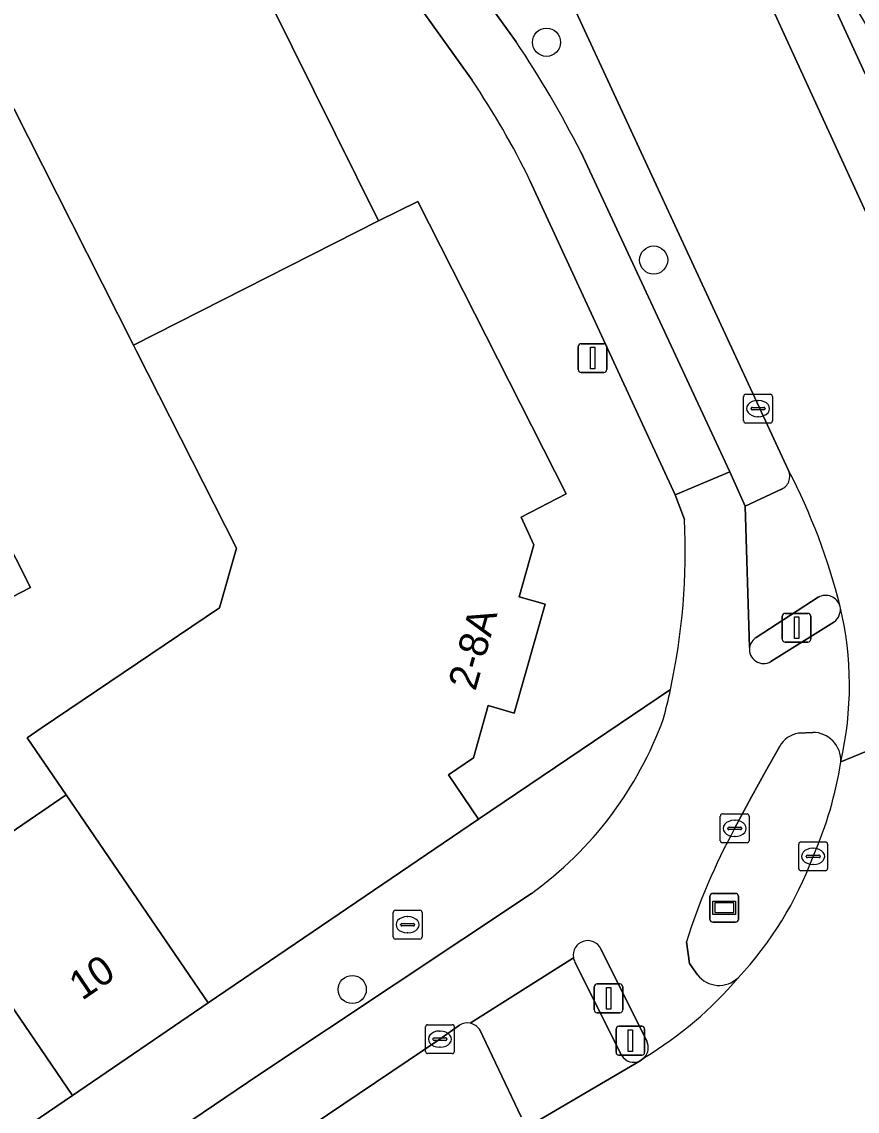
# Model space of a CAD drawing. Extents: x 161838 to 162344, y 381620 to 382160.
# Drawn here: x 162293.12 to 162322.12, y 381677.36 to 381715.15 of the extents above; entities that cross this region are included whole.
import ezdxf

# ---------------------------------------------------------------- set-up
doc = ezdxf.new("R2010")
doc.units = 0
for name, color, linetype in [('IMGEO_Berm_groen', 7, 'Continuous'), ('IMGEO_Boom', 7, 'Continuous'), ('IMGEO_Brandkraan', 7, 'Continuous'), ('IMGEO_Erf', 7, 'Continuous'), ('IMGEO_Fietspad_open', 7, 'Continuous'), ('IMGEO_Kolk', 7, 'Continuous'), ('IMGEO_Lichtmast', 7, 'Continuous'), ('IMGEO_Pand', 7, 'Continuous'), ('IMGEO_Pand_nummerreeks', 7, 'Continuous'), ('IMGEO_Rijbaan_lokaal_gesloten', 7, 'Continuous'), ('IMGEO_Rijbaan_lokaal_open', 7, 'Continuous'), ('IMGEO_Rijbaan_regionaal_gesloten', 7, 'Continuous'), ('IMGEO_Verkeerseiland_open', 7, 'Continuous'), ('IMGEO_Verkeersregelinstallatiepaal', 7, 'Continuous'), ('IMGEO_Voetpad_gesloten', 7, 'Continuous'), ('IMGEO_Voetpad_open', 7, 'Continuous'), ('IMGEO_Wegwijzer', 7, 'Continuous')]:
    doc.layers.add(name, color=color, linetype=linetype)

msp = doc.modelspace()

# ---------------------------------------------------------------- linework, layer by layer
at = {"layer": 'IMGEO_Berm_groen'}
for points in [[(162306.86, 381722.485), (162305.205, 381721.481), (162310.281, 381714.458)], [(162319.738, 381699.582), (162310.249, 381720.064)], [(162312.521, 381710.633), (162317.695, 381699.539), (162318.226, 381698.345), (162319.487, 381698.934)]]:
    msp.add_lwpolyline(points, dxfattribs=at)
for centre, radius, start, end in [((162279.374, 381693.79), 37.181, 26.9367, 33.7715), ((162319.293, 381699.382), 0.488, 293.3838, 24.2689)]:
    msp.add_arc(centre, radius, start, end, dxfattribs=at)
at = {"layer": 'IMGEO_Boom'}
for centre in [(162311.332, 381714.439), (162315.052, 381706.885), (162304.588, 381681.579)]:
    msp.add_circle(centre, 0.489, dxfattribs=at)
at = {"layer": 'IMGEO_Brandkraan'}
for p, q in [((162306.01, 381683.401), (162306.01, 381684.253)), ((162306.085, 381684.327), (162306.937, 381684.327)), ((162307.011, 381684.253), (162307.011, 381683.401)), ((162306.269, 381683.821), (162306.269, 381683.833)), ((162306.312, 381683.87), (162306.71, 381683.87)), ((162306.498, 381684.107), (162306.523, 381684.107)), ((162306.753, 381683.833), (162306.753, 381683.821)), ((162306.707, 381683.784), (162306.309, 381683.784)), ((162306.521, 381683.547), (162306.496, 381683.547)), ((162306.937, 381683.327), (162306.085, 381683.327))]:
    msp.add_line(p, q, dxfattribs=at)
for points in [[(162306.01, 381683.401), (162306.01, 381684.253)], [(162306.085, 381684.327), (162306.937, 381684.327)], [(162307.011, 381684.253), (162307.011, 381683.401)], [(162306.937, 381683.327), (162306.085, 381683.327)]]:
    msp.add_lwpolyline(points, dxfattribs=at)
for centre, radius, start, end in [((162306.087, 381684.251), 0.0765, 91.552, 178.448), ((162306.087, 381684.251), 0.0765, 91.552, 178.448), ((162306.935, 381684.251), 0.0765, 1.552, 88.448), ((162306.935, 381684.251), 0.0765, 1.552, 88.448), ((162306.309, 381683.83), 0.0403, 85.8775, 175.7526), ((162306.306, 381683.82), 0.0366, 178.938, 274.7102), ((162306.71, 381683.827), 0.043, 264.8664, 352.4533), ((162306.714, 381683.832), 0.0386, 1.7309, 96.639), ((162306.087, 381683.403), 0.0765, 181.552, 268.448), ((162306.087, 381683.403), 0.0765, 181.552, 268.448), ((162306.935, 381683.403), 0.0765, 271.552, 358.448), ((162306.935, 381683.403), 0.0765, 271.552, 358.448)]:
    msp.add_arc(centre, radius, start, end, dxfattribs=at)
for centre, major_axis, ratio, start_param, end_param in [((162306.497, 381683.827), (-0.387, 0.002), 0.722429, 4.712389, 7.853982), ((162306.522, 381683.827), (-0.39, 0.002), 0.717154, 1.570796, 4.712389)]:
    msp.add_ellipse(centre, major_axis=major_axis, ratio=ratio, start_param=start_param, end_param=end_param, dxfattribs=at)
at = {"layer": 'IMGEO_Erf'}
for points in [[(162289.948, 381685.116), (162294.655, 381688.332), (162293.298, 381690.315), (162293.785, 381690.643), (162299.981, 381694.821), (162300.565, 381696.886), (162297.099, 381703.727), (162296.995, 381703.932), (162294.839, 381708.188), (162287.364, 381722.942)], [(162290.874, 381700.53), (162293.422, 381695.521), (162291.191, 381694.385)]]:
    msp.add_lwpolyline(points, dxfattribs=at)
at = {"layer": 'IMGEO_Fietspad_open'}
for points in [[(162318.384, 381693.449), (162318.226, 381698.345), (162317.695, 381699.539), (162315.798, 381698.734), (162316.121, 381697.884)], [(162321.313, 381694.326), (162319.125, 381692.96)], [(162320.081, 381690.47), (162320.574, 381690.497)], [(162317.864, 381687.169), (162318.445, 381688.26), (162318.933, 381689.143), (162319.427, 381690.017)], [(162310.812, 381684.914), (162301.343, 381678.613), (162286.165, 381668.36), (162279.678, 381664.016), (162284.442, 381665.356), (162285.99, 381665.89), (162288.456, 381667.106), (162291.599, 381668.782), (162293.515, 381669.819)], [(162316.573, 381682.089), (162316.296, 381682.485), (162316.189, 381683.238)], [(162308.686, 381680.406), (162312.266, 381682.682)], [(162313.219, 381682.99), (162314.814, 381679.786)], [(162307.627, 381679.859), (162308.313, 381680.341)], [(162293.74, 381670.507), (162294.263, 381670.865), (162307.627, 381679.859)]]:
    msp.add_lwpolyline(points, dxfattribs=at)
for centre, radius, start, end in [((162293.525, 381696.773), 22.623, 347.7837, 2.8144), ((162320.985, 381694.769), 0.551, 306.4822, 10.5702), ((162309.989, 381692.125), 11.86, 347.1048, 13.384), ((162318.867, 381693.375), 0.489, 171.2798, 301.877), ((162294.156, 381696.632), 21.977, 345.1018, 347.7945), ((162303.284, 381695.362), 12.877, 305.7717, 340.1147), ((162320.224, 381689.565), 0.916, 98.9778, 150.4398), ((162320.577, 381689.523), 0.974, 357.3695, 90.161), ((162337.855, 381676.328), 22.741, 151.5304, 162.3118), ((162312.765, 381682.768), 0.506, 26.0677, 189.7529), ((162307.977, 381690.441), 13.099, 301.0544, 319.8015), ((162317.323, 381682.671), 0.95, 217.8161, 313.9029), ((162308.582, 381679.902), 0.515, 78.2993, 121.4712), ((162314.363, 381679.561), 0.504, 317.4307, 26.4792)]:
    msp.add_arc(centre, radius, start, end, dxfattribs=at)
at = {"layer": 'IMGEO_Kolk'}
for p, q in [((162318.177, 381701.304), (162318.177, 381702.156)), ((162318.252, 381702.23), (162319.104, 381702.23)), ((162318.665, 381702.01), (162318.69, 381702.01)), ((162319.178, 381702.156), (162319.178, 381701.304)), ((162318.436, 381701.724), (162318.436, 381701.736)), ((162318.874, 381701.687), (162318.476, 381701.687)), ((162318.479, 381701.773), (162318.877, 381701.773)), ((162318.92, 381701.736), (162318.92, 381701.724)), ((162319.104, 381701.23), (162318.252, 381701.23)), ((162318.688, 381701.45), (162318.663, 381701.45)), ((162317.367, 381686.742), (162317.367, 381687.594)), ((162317.442, 381687.668), (162318.294, 381687.668)), ((162318.368, 381687.594), (162318.368, 381686.742)), ((162317.669, 381687.211), (162318.067, 381687.211)), ((162317.855, 381687.448), (162317.88, 381687.448)), ((162317.626, 381687.162), (162317.626, 381687.174)), ((162318.064, 381687.125), (162317.666, 381687.125)), ((162317.878, 381686.888), (162317.853, 381686.888)), ((162318.11, 381687.174), (162318.11, 381687.162)), ((162318.294, 381686.668), (162317.442, 381686.668)), ((162320.089, 381685.771), (162320.089, 381686.623)), ((162320.164, 381686.697), (162321.016, 381686.697)), ((162320.577, 381686.477), (162320.602, 381686.477)), ((162321.09, 381686.623), (162321.09, 381685.771)), ((162320.348, 381686.191), (162320.348, 381686.203)), ((162320.786, 381686.154), (162320.388, 381686.154)), ((162320.391, 381686.24), (162320.789, 381686.24)), ((162320.832, 381686.203), (162320.832, 381686.191)), ((162321.016, 381685.697), (162320.164, 381685.697)), ((162320.6, 381685.917), (162320.575, 381685.917)), ((162307.131, 381679.432), (162307.131, 381680.284)), ((162307.206, 381680.358), (162308.058, 381680.358)), ((162307.619, 381680.138), (162307.644, 381680.138)), ((162308.132, 381680.284), (162308.132, 381679.432)), ((162307.39, 381679.852), (162307.39, 381679.864)), ((162307.828, 381679.815), (162307.43, 381679.815)), ((162307.433, 381679.901), (162307.831, 381679.901)), ((162307.874, 381679.864), (162307.874, 381679.852)), ((162308.058, 381679.358), (162307.206, 381679.358)), ((162307.642, 381679.578), (162307.617, 381679.578))]:
    msp.add_line(p, q, dxfattribs=at)
for points in [[(162318.177, 381701.304), (162318.177, 381702.156)], [(162318.252, 381702.23), (162319.104, 381702.23)], [(162319.178, 381702.156), (162319.178, 381701.304)], [(162319.104, 381701.23), (162318.252, 381701.23)], [(162317.367, 381686.742), (162317.367, 381687.594)], [(162317.442, 381687.668), (162318.294, 381687.668)], [(162318.368, 381687.594), (162318.368, 381686.742)], [(162318.294, 381686.668), (162317.442, 381686.668)], [(162320.089, 381685.771), (162320.089, 381686.623)], [(162320.164, 381686.697), (162321.016, 381686.697)], [(162321.09, 381686.623), (162321.09, 381685.771)], [(162321.016, 381685.697), (162320.164, 381685.697)], [(162307.131, 381679.432), (162307.131, 381680.284)], [(162307.206, 381680.358), (162308.058, 381680.358)], [(162308.132, 381680.284), (162308.132, 381679.432)], [(162308.058, 381679.358), (162307.206, 381679.358)]]:
    msp.add_lwpolyline(points, dxfattribs=at)
for centre, radius, start, end in [((162318.254, 381702.154), 0.0765, 91.552, 178.448), ((162318.254, 381702.154), 0.0765, 91.552, 178.448), ((162319.102, 381702.154), 0.0765, 1.552, 88.448), ((162319.102, 381702.154), 0.0765, 1.552, 88.448), ((162318.476, 381701.733), 0.0403, 85.8775, 175.7526), ((162318.473, 381701.723), 0.0366, 178.938, 274.7102), ((162318.877, 381701.73), 0.043, 264.8664, 352.4533), ((162318.881, 381701.735), 0.0386, 1.7309, 96.639), ((162318.254, 381701.306), 0.0765, 181.552, 268.448), ((162318.254, 381701.306), 0.0765, 181.552, 268.448), ((162319.102, 381701.306), 0.0765, 271.552, 358.448), ((162319.102, 381701.306), 0.0765, 271.552, 358.448), ((162317.444, 381687.592), 0.0765, 91.552, 178.448), ((162317.444, 381687.592), 0.0765, 91.552, 178.448), ((162318.292, 381687.592), 0.0765, 1.552, 88.448), ((162318.292, 381687.592), 0.0765, 1.552, 88.448), ((162317.666, 381687.171), 0.0403, 85.8775, 175.7526), ((162318.071, 381687.173), 0.0386, 1.7309, 96.639), ((162317.663, 381687.161), 0.0366, 178.938, 274.7102), ((162318.067, 381687.168), 0.043, 264.8664, 352.4533), ((162317.444, 381686.744), 0.0765, 181.552, 268.448), ((162317.444, 381686.744), 0.0765, 181.552, 268.448), ((162318.292, 381686.744), 0.0765, 271.552, 358.448), ((162318.292, 381686.744), 0.0765, 271.552, 358.448), ((162320.166, 381686.621), 0.0765, 91.552, 178.448), ((162320.166, 381686.621), 0.0765, 91.552, 178.448), ((162321.014, 381686.621), 0.0765, 1.552, 88.448), ((162321.014, 381686.621), 0.0765, 1.552, 88.448), ((162320.388, 381686.2), 0.0403, 85.8775, 175.7526), ((162320.385, 381686.19), 0.0366, 178.938, 274.7102), ((162320.789, 381686.197), 0.043, 264.8664, 352.4533), ((162320.793, 381686.202), 0.0386, 1.7309, 96.639), ((162320.166, 381685.773), 0.0765, 181.552, 268.448), ((162320.166, 381685.773), 0.0765, 181.552, 268.448), ((162321.014, 381685.773), 0.0765, 271.552, 358.448), ((162321.014, 381685.773), 0.0765, 271.552, 358.448), ((162307.208, 381680.282), 0.0765, 91.552, 178.448), ((162307.208, 381680.282), 0.0765, 91.552, 178.448), ((162308.056, 381680.282), 0.0765, 1.552, 88.448), ((162308.056, 381680.282), 0.0765, 1.552, 88.448), ((162307.43, 381679.861), 0.0403, 85.8775, 175.7526), ((162307.427, 381679.851), 0.0366, 178.938, 274.7102), ((162307.831, 381679.858), 0.043, 264.8664, 352.4533), ((162307.835, 381679.863), 0.0386, 1.7309, 96.639), ((162307.208, 381679.434), 0.0765, 181.552, 268.448), ((162307.208, 381679.434), 0.0765, 181.552, 268.448), ((162308.056, 381679.434), 0.0765, 271.552, 358.448), ((162308.056, 381679.434), 0.0765, 271.552, 358.448)]:
    msp.add_arc(centre, radius, start, end, dxfattribs=at)
for centre, major_axis, ratio, start_param, end_param in [((162318.664, 381701.73), (-0.387, 0.002), 0.722429, 4.712389, 7.853982), ((162318.689, 381701.73), (-0.39, 0.002), 0.717154, 1.570796, 4.712389), ((162317.854, 381687.168), (-0.387, 0.002), 0.722429, 4.712389, 7.853982), ((162317.879, 381687.168), (-0.39, 0.002), 0.717154, 1.570796, 4.712389), ((162320.576, 381686.197), (-0.387, 0.002), 0.722429, 4.712389, 7.853982), ((162320.601, 381686.197), (-0.39, 0.002), 0.717154, 1.570796, 4.712389), ((162307.618, 381679.858), (-0.387, 0.002), 0.722429, 4.712389, 7.853982), ((162307.643, 381679.858), (-0.39, 0.002), 0.717154, 1.570796, 4.712389)]:
    msp.add_ellipse(centre, major_axis=major_axis, ratio=ratio, start_param=start_param, end_param=end_param, dxfattribs=at)
at = {"layer": 'IMGEO_Lichtmast'}
for p, q in [((162312.437, 381703.082), (162312.437, 381703.882)), ((162312.437, 381703.882), (162312.437, 381703.082)), ((162312.537, 381703.982), (162313.327, 381703.982)), ((162313.327, 381703.982), (162312.537, 381703.982)), ((162313.427, 381703.882), (162313.427, 381703.082)), ((162313.427, 381703.082), (162313.427, 381703.882)), ((162313.327, 381702.982), (162312.537, 381702.982)), ((162312.537, 381702.982), (162313.327, 381702.982))]:
    msp.add_line(p, q, dxfattribs=at)
msp.add_lwpolyline([(162312.857, 381703.857), (162313.007, 381703.857), (162313.007, 381703.107), (162312.857, 381703.107), (162312.857, 381703.857)], dxfattribs=at)
for centre, start, end in [((162312.537, 381703.882), 90, 180), ((162312.537, 381703.882), 90, 180), ((162313.327, 381703.882), 0, 90), ((162313.327, 381703.882), 360, 90), ((162312.537, 381703.082), 180, 270), ((162312.537, 381703.082), 180, 270), ((162313.327, 381703.082), 270, 0), ((162313.327, 381703.082), 270, 0)]:
    msp.add_arc(centre, 0.1, start, end, dxfattribs=at)
at = {"layer": 'IMGEO_Pand'}
for points in [[(162296.995, 381703.932), (162305.503, 381708.242), (162301.748, 381715.79), (162303.026, 381716.487), (162300.998, 381720.448), (162299.66, 381719.808), (162295.769, 381727.423), (162287.364, 381722.942), (162294.839, 381708.188)], [(162310.379, 381695.201), (162310.892, 381697.01), (162310.45, 381697.966), (162312.016, 381698.769), (162306.867, 381708.921), (162305.503, 381708.242), (162296.995, 381703.932), (162297.099, 381703.727), (162300.565, 381696.886), (162299.981, 381694.821), (162293.785, 381690.643), (162293.298, 381690.315), (162294.655, 381688.332), (162299.588, 381681.111), (162308.972, 381687.49), (162307.931, 381689.021), (162308.795, 381689.617), (162309.308, 381691.426), (162310.212, 381691.169), (162311.283, 381694.945)], [(162294.655, 381688.332), (162289.948, 381685.116), (162294.874, 381677.907), (162299.588, 381681.111)], [(162289.948, 381685.116), (162285.24, 381681.899), (162290.158, 381674.701), (162294.874, 381677.907)]]:
    msp.add_lwpolyline(points, close=True, dxfattribs=at)
at = {"layer": 'IMGEO_Rijbaan_lokaal_gesloten'}
for points in [[(162326.921, 381698.993), (162325.155, 381702.899), (162324.878, 381703.181), (162301.871, 381753.308)], [(162295.695, 381751.431), (162310.161, 381720.255), (162310.249, 381720.064), (162319.738, 381699.582)], [(162333.756, 381695.892), (162318.739, 381721.3), (162322.39, 381713.347)], [(162321.55, 381689.478), (162328.954, 381692.519), (162328.07, 381695.334), (162326.956, 381698.551), (162326.909, 381698.657)]]:
    msp.add_lwpolyline(points, dxfattribs=at)
for centre, radius, start, end in [((162300.507, 381689.585), 21.674, 14.1133, 27.4671), ((162309.989, 381692.125), 11.86, 347.1048, 13.384)]:
    msp.add_arc(centre, radius, start, end, dxfattribs=at)
at = {"layer": 'IMGEO_Rijbaan_lokaal_open'}
msp.add_lwpolyline([(162291.191, 381694.385), (162293.422, 381695.521), (162290.874, 381700.53)], dxfattribs=at)
at = {"layer": 'IMGEO_Rijbaan_regionaal_gesloten'}
for points in [[(162328.954, 381692.519), (162321.55, 381689.478)], [(162314.734, 381679.22), (162314.585, 381679.105), (162310.64, 381676.791), (162310.287, 381676.584), (162311.76, 381673.667), (162313.323, 381670.573), (162313.719, 381670.825), (162317.538, 381673.258), (162320.432, 381675.065), (162321.734, 381675.903)]]:
    msp.add_lwpolyline(points, dxfattribs=at)
for centre, radius, start, end in [((162308.384, 381691.56), 13.33, 336.2733, 351.0119), ((162308.954, 381690.484), 12.398, 316.735, 339.7695), ((162307.977, 381690.441), 13.099, 301.0544, 319.8015)]:
    msp.add_arc(centre, radius, start, end, dxfattribs=at)
at = {"layer": 'IMGEO_Verkeerseiland_open'}
for points in [[(162301.871, 381753.308), (162324.878, 381703.181), (162325.155, 381702.899), (162325.585, 381702.924), (162326.9, 381703.755)], [(162322.39, 381713.347), (162318.739, 381721.3), (162317.493, 381723.408), (162308.281, 381742.749), (162305.075, 381751.053)], [(162320.762, 381695.184), (162318.609, 381693.79)], [(162319.125, 381692.96), (162321.313, 381694.326)], [(162320.574, 381690.497), (162320.081, 381690.47)], [(162319.427, 381690.017), (162318.933, 381689.143), (162318.445, 381688.26), (162317.864, 381687.169)], [(162316.189, 381683.238), (162316.296, 381682.485), (162316.573, 381682.089)], [(162314.814, 381679.786), (162313.219, 381682.99)], [(162312.317, 381682.533), (162313.932, 381679.299)], [(162308.313, 381680.341), (162307.627, 381679.859), (162294.263, 381670.865), (162293.74, 381670.507)], [(162310.457, 381677.165), (162309.004, 381680.2)], [(162314.585, 381679.105), (162314.734, 381679.22)]]:
    msp.add_lwpolyline(points, dxfattribs=at)
for centre, radius, start, end in [((162321.019, 381694.721), 0.529, 16.3066, 119.0612), ((162320.985, 381694.769), 0.551, 306.4822, 10.5702), ((162318.867, 381693.375), 0.488, 121.8455, 171.3189), ((162318.867, 381693.375), 0.489, 171.2798, 301.877), ((162320.224, 381689.565), 0.916, 98.9778, 150.4398), ((162320.577, 381689.523), 0.974, 357.3695, 90.161), ((162308.384, 381691.56), 13.33, 336.2733, 351.0119), ((162337.855, 381676.328), 22.741, 151.5304, 162.3118), ((162308.954, 381690.484), 12.398, 316.735, 339.7695), ((162312.765, 381682.768), 0.506, 26.0677, 189.7529), ((162312.804, 381682.783), 0.548, 190.6298, 207.1605), ((162317.323, 381682.671), 0.95, 217.8161, 313.9029), ((162308.582, 381679.902), 0.515, 78.2993, 121.4712), ((162308.584, 381679.9), 0.516, 35.5152, 78.6145), ((162314.363, 381679.561), 0.504, 317.4307, 26.4792), ((162314.364, 381679.558), 0.504, 210.9635, 295.9441)]:
    msp.add_arc(centre, radius, start, end, dxfattribs=at)
at = {"layer": 'IMGEO_Verkeersregelinstallatiepaal'}
for p, q in [((162319.517, 381693.728), (162319.517, 381694.528)), ((162319.517, 381694.528), (162319.517, 381693.728)), ((162319.617, 381694.628), (162320.407, 381694.628)), ((162320.407, 381694.628), (162319.617, 381694.628)), ((162320.507, 381694.528), (162320.507, 381693.728)), ((162320.507, 381693.728), (162320.507, 381694.528)), ((162320.407, 381693.628), (162319.617, 381693.628)), ((162319.617, 381693.628), (162320.407, 381693.628)), ((162312.99, 381680.872), (162312.99, 381681.672)), ((162312.99, 381681.672), (162312.99, 381680.872)), ((162313.09, 381681.772), (162313.88, 381681.772)), ((162313.88, 381681.772), (162313.09, 381681.772)), ((162313.98, 381681.672), (162313.98, 381680.872)), ((162313.98, 381680.872), (162313.98, 381681.672)), ((162313.88, 381680.772), (162313.09, 381680.772)), ((162313.09, 381680.772), (162313.88, 381680.772)), ((162313.748, 381679.403), (162313.748, 381680.203)), ((162313.748, 381680.203), (162313.748, 381679.403)), ((162313.848, 381680.303), (162314.638, 381680.303)), ((162314.638, 381680.303), (162313.848, 381680.303)), ((162314.738, 381680.203), (162314.738, 381679.403)), ((162314.738, 381679.403), (162314.738, 381680.203)), ((162314.638, 381679.303), (162313.848, 381679.303)), ((162313.848, 381679.303), (162314.638, 381679.303))]:
    msp.add_line(p, q, dxfattribs=at)
for points in [[(162319.937, 381694.503), (162320.087, 381694.503), (162320.087, 381693.753), (162319.937, 381693.753), (162319.937, 381694.503)], [(162313.41, 381681.647), (162313.56, 381681.647), (162313.56, 381680.897), (162313.41, 381680.897), (162313.41, 381681.647)], [(162314.168, 381680.178), (162314.318, 381680.178), (162314.318, 381679.428), (162314.168, 381679.428), (162314.168, 381680.178)]]:
    msp.add_lwpolyline(points, dxfattribs=at)
for centre, start, end in [((162319.617, 381694.528), 90, 180), ((162319.617, 381694.528), 90, 180), ((162320.407, 381694.528), 0, 90), ((162320.407, 381694.528), 360, 90), ((162319.617, 381693.728), 180, 270), ((162319.617, 381693.728), 180, 270), ((162320.407, 381693.728), 270, 0), ((162320.407, 381693.728), 270, 0), ((162313.09, 381681.672), 90, 180), ((162313.09, 381681.672), 90, 180), ((162313.88, 381681.672), 0, 90), ((162313.88, 381681.672), 360, 90), ((162313.09, 381680.872), 180, 270), ((162313.09, 381680.872), 180, 270), ((162313.88, 381680.872), 270, 0), ((162313.88, 381680.872), 270, 0), ((162313.848, 381680.203), 90, 180), ((162313.848, 381680.203), 90, 180), ((162314.638, 381680.203), 0, 90), ((162314.638, 381680.203), 360, 90), ((162313.848, 381679.403), 180, 270), ((162313.848, 381679.403), 180, 270), ((162314.638, 381679.403), 270, 0), ((162314.638, 381679.403), 270, 0)]:
    msp.add_arc(centre, 0.1, start, end, dxfattribs=at)
at = {"layer": 'IMGEO_Voetpad_gesloten'}
for points in [[(162310.281, 381714.458), (162305.205, 381721.481), (162304.396, 381722.807), (162303.141, 381725.051), (162301.083, 381729.14), (162298.402, 381735.121), (162297.795, 381736.557), (162293.643, 381747.456), (162291.289, 381753.398), (162289.504, 381757.563)], [(162304.099, 381719.625), (162308.746, 381713.124)], [(162310.756, 381709.646), (162315.798, 381698.734), (162317.695, 381699.539), (162312.521, 381710.633)]]:
    msp.add_lwpolyline(points, dxfattribs=at)
for centre, radius, start, end in [((162279.374, 381693.79), 37.181, 26.9367, 33.7715), ((162285.423, 381697.325), 28.17, 25.9358, 34.113)]:
    msp.add_arc(centre, radius, start, end, dxfattribs=at)
at = {"layer": 'IMGEO_Voetpad_open'}
for points in [[(162292.991, 381732.858), (162295.769, 381727.423), (162299.66, 381719.808), (162300.998, 381720.448), (162303.026, 381716.487), (162301.748, 381715.79), (162305.503, 381708.242), (162306.867, 381708.921), (162312.016, 381698.769), (162310.45, 381697.966), (162310.892, 381697.01), (162310.379, 381695.201), (162311.283, 381694.945), (162310.212, 381691.169), (162309.308, 381691.426), (162308.795, 381689.617), (162307.931, 381689.021), (162308.972, 381687.49), (162315.636, 381691.986)], [(162308.746, 381713.124), (162304.099, 381719.625)], [(162316.121, 381697.884), (162315.798, 381698.734), (162310.756, 381709.646)], [(162319.487, 381698.934), (162318.226, 381698.345), (162318.384, 381693.449)], [(162318.609, 381693.79), (162320.762, 381695.184)], [(162315.636, 381691.986), (162308.972, 381687.49), (162299.588, 381681.111), (162294.874, 381677.907), (162290.158, 381674.701)], [(162241.048, 381649.166), (162243.686, 381649.981), (162246.43, 381650.83), (162257.303, 381654.644), (162264.812, 381657.392), (162272.909, 381660.74), (162277.242, 381662.769), (162279.678, 381664.016), (162286.165, 381668.36), (162301.343, 381678.613), (162310.812, 381684.914)], [(162312.266, 381682.682), (162308.686, 381680.406)], [(162313.932, 381679.299), (162312.317, 381682.533)], [(162309.004, 381680.2), (162310.457, 381677.165)], [(162310.287, 381676.584), (162310.64, 381676.791), (162314.585, 381679.105)]]:
    msp.add_lwpolyline(points, dxfattribs=at)
for centre, radius, start, end in [((162285.423, 381697.325), 28.17, 25.9358, 34.113), ((162319.293, 381699.382), 0.488, 293.3838, 24.2689), ((162300.507, 381689.585), 21.674, 14.1133, 27.4671), ((162293.525, 381696.773), 22.623, 347.7837, 2.8144), ((162321.019, 381694.721), 0.529, 16.3066, 119.0612), ((162318.867, 381693.375), 0.488, 121.8455, 171.3189), ((162294.156, 381696.632), 21.977, 345.1018, 347.7945), ((162303.284, 381695.362), 12.877, 305.7717, 340.1147), ((162312.804, 381682.783), 0.548, 190.6298, 207.1605), ((162308.584, 381679.9), 0.516, 35.5152, 78.6145), ((162314.364, 381679.558), 0.504, 210.9635, 295.9441)]:
    msp.add_arc(centre, radius, start, end, dxfattribs=at)
at = {"layer": 'IMGEO_Wegwijzer'}
for p, q in [((162317.007, 381684.013), (162317.007, 381684.813)), ((162317.007, 381684.813), (162317.007, 381684.013)), ((162317.107, 381684.913), (162317.897, 381684.913)), ((162317.897, 381684.913), (162317.107, 381684.913)), ((162317.997, 381684.813), (162317.997, 381684.013)), ((162317.997, 381684.013), (162317.997, 381684.813)), ((162317.897, 381683.913), (162317.107, 381683.913)), ((162317.107, 381683.913), (162317.897, 381683.913))]:
    msp.add_line(p, q, dxfattribs=at)
for points in [[(162317.108, 381684.645), (162317.896, 381684.645), (162317.896, 381684.181), (162317.108, 381684.181), (162317.108, 381684.645)], [(162317.173, 381684.58), (162317.173, 381684.246), (162317.831, 381684.246), (162317.831, 381684.58), (162317.173, 381684.58)]]:
    msp.add_lwpolyline(points, dxfattribs=at)
for centre, start, end in [((162317.107, 381684.813), 90, 180), ((162317.107, 381684.813), 90, 180), ((162317.897, 381684.813), 0, 90), ((162317.897, 381684.813), 360, 90), ((162317.107, 381684.013), 180, 270), ((162317.107, 381684.013), 180, 270), ((162317.897, 381684.013), 270, 0), ((162317.897, 381684.013), 270, 0)]:
    msp.add_arc(centre, 0.1, start, end, dxfattribs=at)

# ---------------------------------------------------------------- texts
at = {"layer": 'IMGEO_Pand_nummerreeks'}
for s, rotation, p in [('2-8A', 74.1637, (162308.863, 381691.909)), ('10', 34.2064, (162295.204, 381681.178))]:
    msp.add_text(s, height=1, rotation=rotation, dxfattribs=at).set_placement(p)

doc.saveas('drawing.dxf')
